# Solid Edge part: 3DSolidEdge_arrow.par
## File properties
Author: Administrator
Last saved by: Administrator
Revision: 50
Accuracy: 0.990
Agile_Description: Arrow Control Pad
Modeled_By: L. Conard
Part_Number: ITEM-SE-00008
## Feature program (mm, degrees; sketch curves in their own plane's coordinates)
body "unnamed Body 1"
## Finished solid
Body 1: solid body, 50 faces, 120 edges, 72 vertices.
  Faces by surface: plane 26, cylinder 24
  Edges by curve: line 96, ellipse 24
Bounding box of the edges (mm): 28.000 x 28.000 x 3.000, from (-19.7427, 35.9821, 0) to (8.2573, 63.9821, 3).
Cylindrical faces by radius (mm): R0.5 x24
Planar faces by outward normal: +x 4, +y 4, +z 1, -x 4, -y 4, -z 1, oblique 8
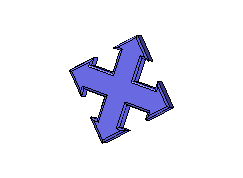
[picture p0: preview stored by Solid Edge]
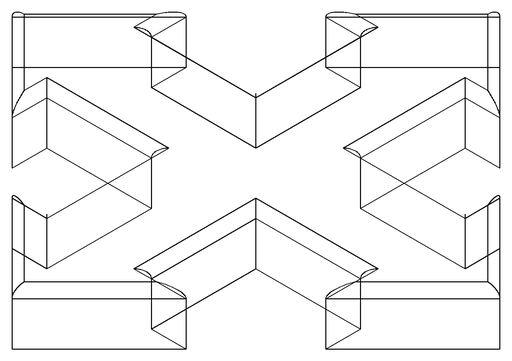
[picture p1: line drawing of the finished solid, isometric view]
